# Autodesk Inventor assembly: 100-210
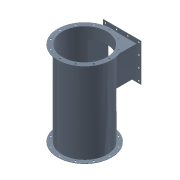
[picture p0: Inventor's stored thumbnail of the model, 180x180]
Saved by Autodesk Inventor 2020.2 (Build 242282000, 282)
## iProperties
Created: 2011-01
Part Number: 100-210
Document SubType Name: Konstrukcja spawana
Designer: F.Stasiak
Weld Material: Spawane aluminium-6061
Company: Fabian Stasiak CAD Consulting
Manager: www.cadconsulting.pl
Author: F.Stasiak
Subject: Zbiór ćwiczeń. Autodesk Inventor 2020. Kurs podstawowy
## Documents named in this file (3)
- C:\2020_Kurs_podstawowy\R6 Zespoły\Kolizja\100-210.iam
- C:\2020_Kurs_podstawowy\R6 Zespoły\Kolizja\100-211.ipt
- C:\2020_Kurs_podstawowy\R6 Zespoły\Kolizja\100-212.ipt
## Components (2 placed, 2 different names)
1. 100-211:1 — Zestawiający:1, Styczny:1, Równoległy:1
2. 100-212:1 — Zestawiający:1, Styczny:1, Równoległy:1
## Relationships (3: Mate 1, Tangent 1, Flush 1)
- Zestawiający:1 [Mate]: 100-211:1 ↔ 100-212:1
- Styczny:1 [Tangent]: 100-211:1 ↔ 100-212:1
- Równoległy:1 [Flush]: 100-211:1 ↔ 100-212:1
